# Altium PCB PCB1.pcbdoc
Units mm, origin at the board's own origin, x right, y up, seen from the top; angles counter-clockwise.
Board outline 23.26 x 24.6 mm, 2 copper layers (Top Layer, Bottom Layer), stack 1.58 mm thick; 1 components, 0 nets, 16 pads, 0 vias.
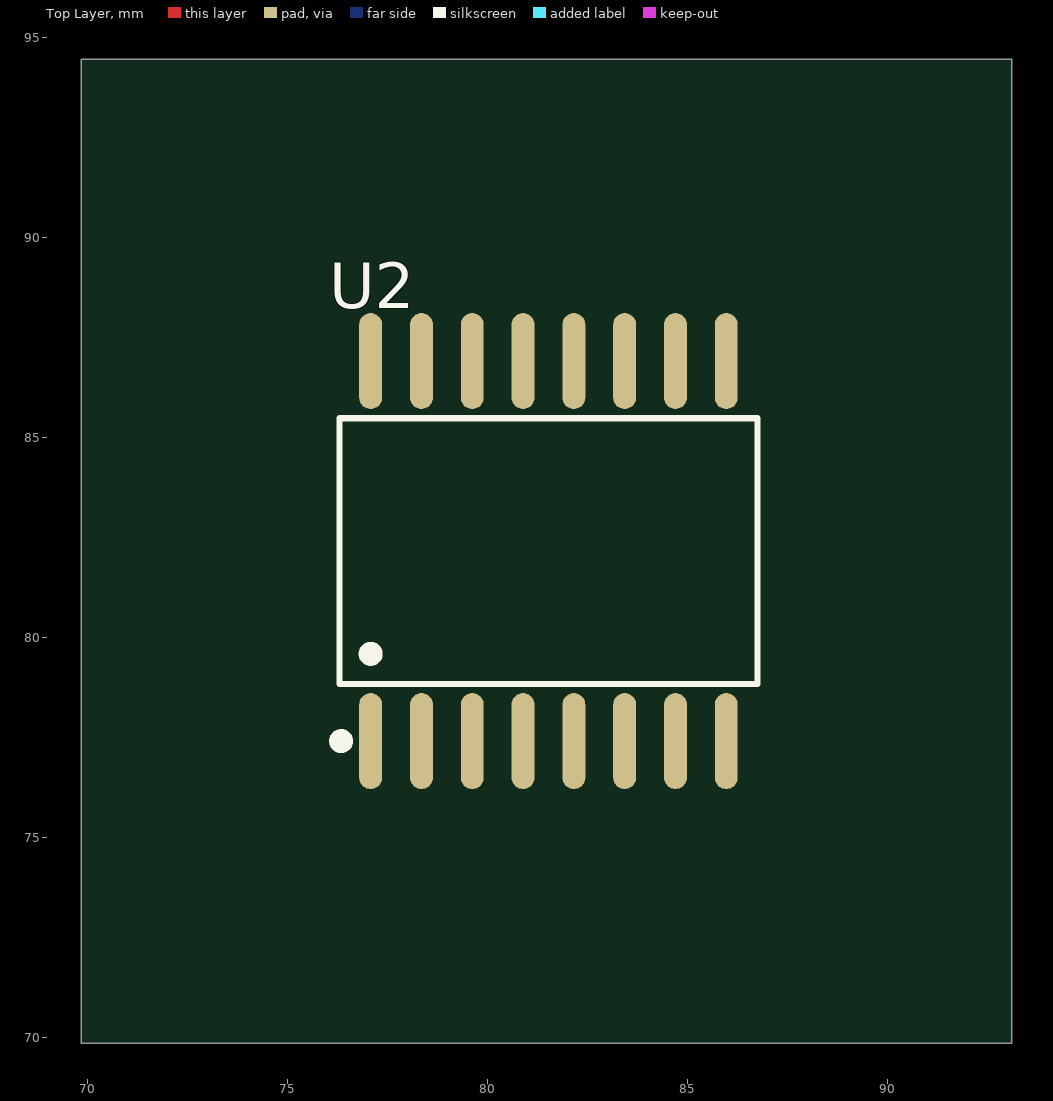
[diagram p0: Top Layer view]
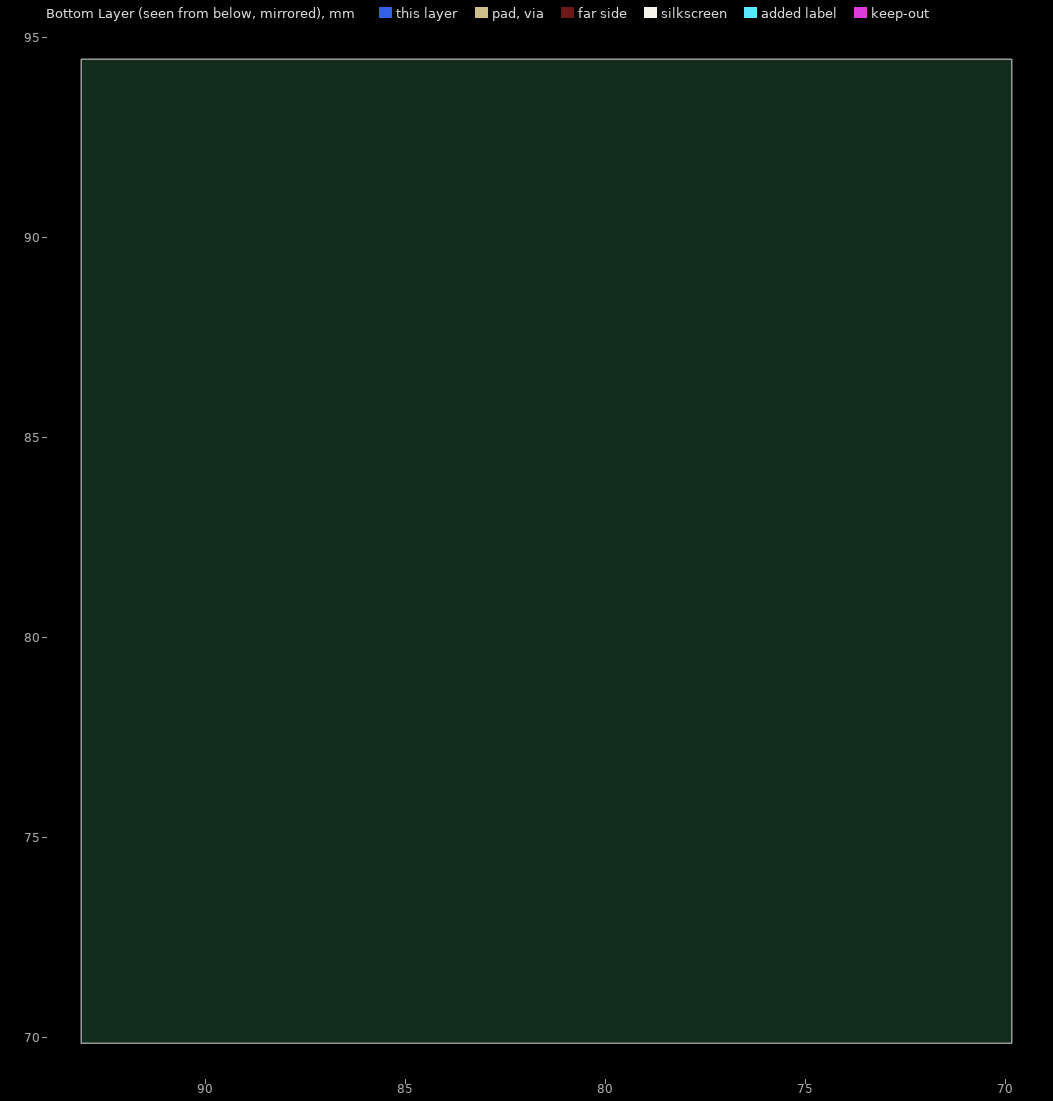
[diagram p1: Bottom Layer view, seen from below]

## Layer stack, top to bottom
Top Solder Mask Layer: solder mask 0.01, Dk 3.3
Top Layer: signal copper 0.035
Dielectric1: surface 1.51, FR4, Dk 4.5
Bottom Layer: signal copper 0.035
Bottom Solder Mask Layer: solder mask 0.01, Dk 3.3

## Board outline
93.111,69.85 69.85,69.85 69.85,94.451 93.111,94.451

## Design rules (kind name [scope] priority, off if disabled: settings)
BoardOutlineClearance copperThickness1oz [All] p0: genericclearance=0.254 ignorepadtopadclearanceinfootprint=FALSE except(0: Arc-SplitContinuation Track-SplitContinuation SMDPad-SplitContinuation THPad-SplitContinuation Via-SplitContinuation Fill-SplitContinuation Poly-SplitContinuation Region-SplitContinuation Text-SplitContinuation)
BoardOutlineClearance copperThickness2oz [All] p0: genericclearance=0.254 ignorepadtopadclearanceinfootprint=FALSE except(0: Arc-SplitContinuation Track-SplitContinuation SMDPad-SplitContinuation THPad-SplitContinuation Via-SplitContinuation Fill-SplitContinuation Poly-SplitContinuation Region-SplitContinuation Text-SplitContinuation)
BoardOutlineClearance otherClearance [All] p0: genericclearance=0.254 ignorepadtopadclearanceinfootprint=FALSE except(0: Arc-SplitContinuation Track-SplitContinuation SMDPad-SplitContinuation THPad-SplitContinuation Via-SplitContinuation Fill-SplitContinuation Poly-SplitContinuation Region-SplitContinuation Text-SplitContinuation)
Clearance copperThickness1oz [All] p1: gap=0.178 ignorepadtopadclearanceinfootprint=FALSE
Clearance copperThickness2oz [All] p1: gap=0.178 ignorepadtopadclearanceinfootprint=FALSE
Clearance otherClearance [All] p1: gap=0.178 ignorepadtopadclearanceinfootprint=FALSE
DiffPairsRouting differentialPair [All] p1: maxuncoupledlength=10 minlimit=6 maxlimit=Infinity mostfreqgap=6 toplayer_minwidth=5 toplayer_prefwidth=10 toplayer_maxwidth=100 bottomlayer_minwidth=5 bottomlayer_prefwidth=10 bottomlayer_maxwidth=100
PasteMaskExpansion pasteMaskExpansion [All] p1: expansion=0
PlaneConnect innerPlane [All] p1: planeconnectstyle=Relief reliefexpansion=0.508 reliefentries=4 reliefconductorwidth=0.254 reliefairgap=0.254
PolygonConnect copperRegion [All] p1: connectstyle=Relief reliefentries=4 reliefconductorwidth=10 polygonreliefangle="90 Angle" airgapwidth=10
RoutingVias viaSize [All] p1: viastyle="Through Hole" holewidth=12.0078 minholewidth=11.811 maxholewidth=248.0314 width=12.0078 minwidth=11.811 maxwidth=248.0314
SolderMaskExpansion solderMaskExpansion [All] p1: useseparateexpansions=TRUE expansion=2 expansionbottom=2
Width copperThickness1oz [All] p1: maxlimit=100 minlimit=5 preferedwidth=10
Width copperThickness2oz [All] p1: maxlimit=100 minlimit=8 preferedwidth=10

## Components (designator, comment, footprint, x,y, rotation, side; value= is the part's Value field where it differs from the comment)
U2 "" SOIC-16_L10.3-W7.5-P1.27-LS10.3-BL 81.535,82.151 r0 top

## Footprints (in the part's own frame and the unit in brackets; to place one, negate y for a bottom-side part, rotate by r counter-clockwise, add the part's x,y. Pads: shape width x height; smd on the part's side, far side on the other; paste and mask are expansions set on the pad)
SOIC-16_L10.3-W7.5-P1.27-LS10.3-BL [mm]
  oval 0.574x2.401 smd: 1(-4.445,-4.75) 2(-3.175,-4.75) 3(-1.905,-4.75) 4(-0.635,-4.75) 5(0.635,-4.75) 6(1.905,-4.75) 7(3.175,-4.75) 8(4.445,-4.75) 9(4.445,4.75) 10(3.175,4.75) 11(1.905,4.75) 12(0.635,4.75) 13(-0.635,4.75) 14(-1.905,4.75) 15(-3.175,4.75) 16(-4.445,4.75)
  silkscreen extent -5.33,-4.9 5.23,3.32

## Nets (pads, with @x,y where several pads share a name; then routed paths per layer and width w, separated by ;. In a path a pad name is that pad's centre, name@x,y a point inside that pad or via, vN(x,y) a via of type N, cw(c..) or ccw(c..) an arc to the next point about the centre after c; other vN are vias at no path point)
pads on no net: U2.1 U2.2 U2.3 U2.4 U2.5 U2.6 U2.7 U2.8 U2.9 U2.10 U2.11 U2.12 U2.13 U2.14 U2.15 U2.16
